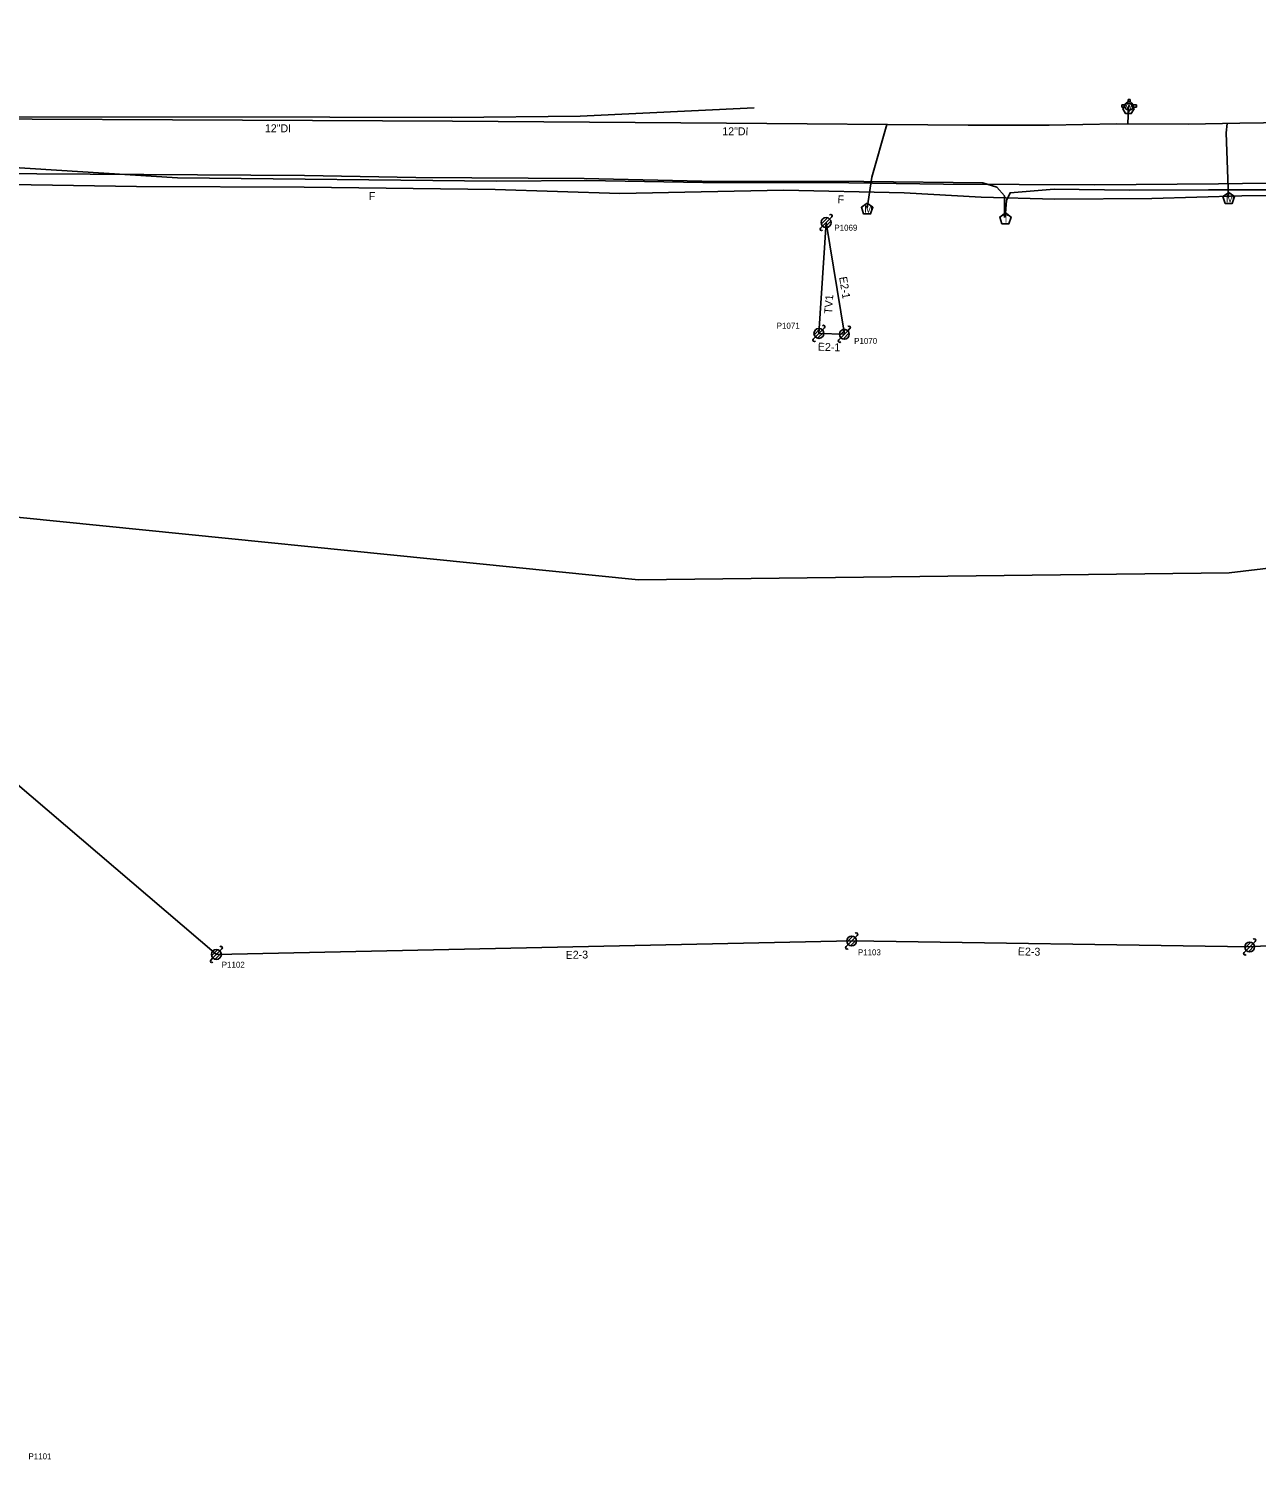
# Model space of a CAD drawing. Extents: x 1614474 to 1865144, y 1098877 to 1212550.
# Drawn here: x 1802379 to 1802999, y 1187603 to 1188326 of the extents above; entities that cross this region are included whole.
import ezdxf

# ---------------------------------------------------------------- set-up
doc = ezdxf.new("R2010")
doc.units = 0
for name, color, linetype in [('BFUSER_FIBERSPAN', 7, 'Continuous'), ('RD_EX_SU_Gas', 7, 'Continuous'), ('RD_EX_SU_H2O', 7, 'Continuous'), ('RD_EX_SU_Ovhd', 7, 'Continuous'), ('RD_EX_SU_Pole', 7, 'Continuous'), ('RD_EX_SU_Telecom', 7, 'Continuous'), ('RD_EX_SU_TX_H2O', 7, 'Continuous'), ('RD_EX_SU_TX_Pole', 7, 'Continuous'), ('RD_EX_SU_TX_Telecom', 7, 'Continuous')]:
    doc.layers.add(name, color=color, linetype=linetype)

# ---------------------------------------------------------------- blocks, each defined once
blk = doc.blocks.new('SUE_TPP')
at = {"layer": 'RD_EX_SU_Telecom'}
blk.add_lwpolyline([(0, 3), (-2.85, 0.93), (-1.76, -2.43), (1.76, -2.43), (2.85, 0.93)], close=True, dxfattribs=at)
blk.add_text('T', height=3.75, dxfattribs=at).set_placement((-1.25, -1.88))
blk = doc.blocks.new('SUE_WV')
at = {"layer": 'RD_EX_SU_H2O'}
blk.add_lwpolyline([(2.89, 0), (1.44, 2.5), (-1.44, 2.5), (-2.89, 0), (-1.44, -2.5), (1.44, -2.5)], close=True, dxfattribs=at)
blk.add_text('V', height=3.75, dxfattribs=at).set_placement((-1.43, -1.88))
blk = doc.blocks.new('SUE_WFH')
at = {"layer": 'RD_EX_SU_H2O'}
for p, q in [((-2.01, 0.6), (-3.65, 0.6)), ((-3.65, 0.6), (-3.65, -0.45)), ((-0.48, 3.38), (-0.48, 2.04)), ((0.57, 3.38), (-0.48, 3.38)), ((0.57, 2.02), (0.57, 3.38)), ((3.7, 0.6), (2.01, 0.6)), ((3.7, -0.45), (3.7, 0.6)), ((-3.65, -0.45), (-2.05, -0.45)), ((2.05, -0.45), (3.7, -0.45))]:
    blk.add_line(p, q, dxfattribs=at)
for radius in [2.1, 0.263]:
    blk.add_circle((0, 0), radius, dxfattribs=at)
for start, end in [(163.3387, 192.31502), (74.24552, 103.21276), (347.68498, 16.6613)]:
    blk.add_arc((0, 0), 2.1, start, end, dxfattribs=at)
blk = doc.blocks.new('SUE_WM')
at = {"layer": 'RD_EX_SU_H2O'}
blk.add_lwpolyline([(0, 3.05), (-2.9, 0.94), (-1.79, -2.47), (1.79, -2.47), (2.9, 0.94)], close=True, dxfattribs=at)
blk.add_text('M', height=3.75, dxfattribs=at).set_placement((-1.43, -1.88))
blk = doc.blocks.new('SUE_PP')
at = {"layer": 'RD_EX_SU_Pole'}
for p, q in [((-2.41, -0.65), (0.65, 2.41)), ((-1.77, -1.77), (1.77, 1.77)), ((-0.65, -2.41), (2.41, 0.65)), ((1.77, 1.77), (2.83, 2.83)), ((-2.83, -2.83), (-1.77, -1.77))]:
    blk.add_line(p, q, dxfattribs=at)
blk.add_circle((0, 0), 2.5, dxfattribs=at)
for centre, start, end in [((2.3, 3.36), 315, 135), ((-2.3, -3.36), 135, 315)]:
    blk.add_arc(centre, 0.75, start, end, dxfattribs=at)

msp = doc.modelspace()

# ---------------------------------------------------------------- linework, layer by layer
at = {"layer": 'BFUSER_FIBERSPAN'}
msp.add_lwpolyline([(1801787.69, 1188212.97), (1801798.88, 1188211.88), (1801776.62, 1188143.66), (1802332.91, 1188082.99), (1802687.07, 1188047.3), (1802985.23, 1188050.78), (1803198.95, 1188076.24)], dxfattribs=at)
at = {"layer": 'RD_EX_SU_Gas'}
msp.add_lwpolyline([(1802035.69, 1188325.53), (1802038.75, 1188311.1), (1802040.95, 1188290.73), (1802043.42, 1188284.85), (1802048.92, 1188285.96), (1802064.02, 1188285.5), (1802120.55, 1188282.05), (1802217.43, 1188282.09), (1802363.14, 1188281), (1802531.2, 1188280.89), (1802592.84, 1188280.65), (1802657.49, 1188281.38), (1802745.41, 1188285.57)], dxfattribs=at)
at = {"layer": 'RD_EX_SU_H2O'}
msp.add_line((1802934.02, 1188277.42), (1802934.36, 1188286.11), dxfattribs=at)
for points in [[(1801857.46, 1188285.91), (1801907.01, 1188284.1), (1801950.85, 1188283.21), (1801982.92, 1188283.18), (1802021.22, 1188283.03), (1802053.57, 1188283.05), (1802102.06, 1188281.72), (1802239.26, 1188280.4), (1802593.05, 1188278.81), (1802731.51, 1188277.72), (1802853.5, 1188276.84), (1802894.3, 1188276.72), (1802928.34, 1188277.44), (1802964.61, 1188277.33), (1802990.65, 1188277.72), (1803038.29, 1188278.47)], [(1802802.43, 1188234.93), (1802804.85, 1188250.6), (1802812.38, 1188277.14)], [(1802984.18, 1188277.63), (1802983.75, 1188272.95), (1802984.85, 1188240.4)]]:
    msp.add_lwpolyline(points, dxfattribs=at)
at = {"layer": 'RD_EX_SU_Ovhd'}
for p, q in [((1802778.1, 1188171.63), (1802781.75, 1188227.63)), ((1802781.75, 1188227.63), (1802790.96, 1188171.22)), ((1802778.1, 1188171.63), (1802790.96, 1188171.22)), ((1802152.75, 1188132.38), (1802473.88, 1187858.09)), ((1802995.59, 1187861.88), (1803204.4, 1187874.28)), ((1802473.88, 1187858.09), (1802794.65, 1187864.89)), ((1802794.65, 1187864.89), (1802995.59, 1187861.88))]:
    msp.add_line(p, q, dxfattribs=at)
at = {"layer": 'RD_EX_SU_Pole'}
for p, q in [((1802775.27, 1188168.8), (1802776.33, 1188169.86)), ((1802775.68, 1188170.98), (1802778.74, 1188174.04)), ((1802776.33, 1188169.86), (1802779.87, 1188173.39)), ((1802777.45, 1188169.21), (1802780.51, 1188172.27)), ((1802779.87, 1188173.39), (1802780.93, 1188174.46)), ((1802788.13, 1188168.39), (1802789.2, 1188169.45)), ((1802788.55, 1188170.57), (1802791.61, 1188173.63)), ((1802789.2, 1188169.45), (1802792.73, 1188172.99)), ((1802790.32, 1188168.8), (1802793.38, 1188171.86)), ((1802792.73, 1188172.99), (1802793.79, 1188174.05)), ((1802792.23, 1187864.24), (1802795.29, 1187867.3)), ((1802792.88, 1187863.12), (1802796.41, 1187866.65)), ((1802794, 1187862.47), (1802797.06, 1187865.53)), ((1802796.41, 1187866.65), (1802797.47, 1187867.71)), ((1802471.46, 1187857.44), (1802474.52, 1187860.5)), ((1802472.11, 1187856.32), (1802475.64, 1187859.86)), ((1802473.23, 1187855.67), (1802476.29, 1187858.74)), ((1802475.64, 1187859.86), (1802476.7, 1187860.92)), ((1802791.82, 1187862.06), (1802792.88, 1187863.12)), ((1802992.76, 1187859.05), (1802993.82, 1187860.11)), ((1802993.17, 1187861.23), (1802996.24, 1187864.29)), ((1802993.82, 1187860.11), (1802997.36, 1187863.65)), ((1802994.94, 1187859.46), (1802998, 1187862.53)), ((1802997.36, 1187863.65), (1802998.42, 1187864.71)), ((1802471.05, 1187855.26), (1802472.11, 1187856.32))]:
    msp.add_line(p, q, dxfattribs=at)
for centre in [(1802778.1, 1188171.63), (1802790.96, 1188171.22), (1802794.65, 1187864.89), (1802473.88, 1187858.09), (1802995.59, 1187861.88)]:
    msp.add_circle(centre, 2.5, dxfattribs=at)
for centre, start, end in [((1802775.8, 1188168.27), 135, 315), ((1802780.4, 1188174.99), 315, 135), ((1802793.26, 1188174.58), 315, 135), ((1802788.66, 1188167.86), 135, 315), ((1802796.94, 1187868.25), 315, 135), ((1802997.89, 1187865.24), 315, 135), ((1802476.17, 1187861.45), 315, 135), ((1802792.35, 1187861.53), 135, 315), ((1802993.29, 1187858.52), 135, 315), ((1802471.58, 1187854.73), 135, 315)]:
    msp.add_arc(centre, 0.75, start, end, dxfattribs=at)
at = {"layer": 'RD_EX_SU_Telecom'}
for points in [[(1801862.35, 1188317.37), (1801873.43, 1188312.99), (1801883.86, 1188304.45), (1801891.39, 1188294.55), (1801895.78, 1188281.09), (1801898.32, 1188280.05), (1801896.15, 1188256.89), (1801899.35, 1188255.07), (1801932.38, 1188254.92), (1801976.57, 1188255.02), (1802034.35, 1188254.03), (1802096.1, 1188253.61), (1802230.47, 1188252.94), (1802355.95, 1188252.37), (1802518.32, 1188251.31), (1802574.51, 1188250.38), (1802659.53, 1188249.82), (1802718.99, 1188248.54), (1802800.77, 1188248.26), (1802860.92, 1188247.72), (1802867.92, 1188245.53), (1802871.84, 1188241.03), (1802871.83, 1188230.11)], [(1801968.17, 1188243.8), (1801975.11, 1188252.56), (1801995.47, 1188251.98), (1802119.14, 1188251.93), (1802254.07, 1188252.11), (1802355.76, 1188256.39), (1802454.16, 1188250.22), (1802615.38, 1188248.45), (1802660.58, 1188248.77), (1802719.54, 1188247.91), (1802781.2, 1188247.75), (1802841.08, 1188246.91), (1802917.35, 1188246.59), (1802979.82, 1188247.18), (1803040.76, 1188247.99), (1803094.59, 1188247.87), (1803108.84, 1188247.38), (1803112.58, 1188243.21)], [(1801967.37, 1188243.92), (1801984.85, 1188243.7), (1802015.11, 1188247.25), (1802055.06, 1188247.37), (1802097.38, 1188247.06), (1802166.97, 1188247.83), (1802252.78, 1188247.03), (1802337.76, 1188247.32), (1802433.59, 1188245.79), (1802518.24, 1188245.41), (1802614.63, 1188244.32), (1802677.58, 1188242.3), (1802718.6, 1188243.19), (1802760.44, 1188243.9), (1802821.17, 1188242.63), (1802859.98, 1188240.47), (1802897.26, 1188239.34), (1802946.24, 1188239.68), (1802991.69, 1188241.06), (1803061.1, 1188241.67)], [(1802872.16, 1188230.26), (1802872.81, 1188238.73), (1802874.65, 1188242.69), (1802896.97, 1188244.53), (1802935, 1188243.9), (1802974.87, 1188244.14), (1803007.78, 1188244.14), (1803058.19, 1188245.26), (1803106.18, 1188244.65), (1803115.09, 1188243.42), (1803117.49, 1188239.07)]]:
    msp.add_lwpolyline(points, dxfattribs=at)

# ---------------------------------------------------------------- block references
at = {"layer": 'RD_EX_SU_H2O'}
for name, p in [('SUE_WFH', (1802934.7, 1188286.4)), ('SUE_WV', (1802934.41, 1188285.09)), ('SUE_WM', (1802985.03, 1188239.76)), ('SUE_WM', (1802802.44, 1188234.42))]:
    msp.add_blockref(name, p, dxfattribs=at)
at = {"layer": 'RD_EX_SU_Pole'}
msp.add_blockref('SUE_PP', (1802781.75, 1188227.63), dxfattribs=at)
at = {"layer": 'RD_EX_SU_Telecom'}
msp.add_blockref('SUE_TPP', (1802872.28, 1188229.47), dxfattribs=at)

# ---------------------------------------------------------------- texts
at = {"layer": 'RD_EX_SU_Ovhd'}
for s, rotation, p in [('E2-1', 279.27619, (1802788.29, 1188200)), ('TV1', 86.26999, (1802784.75, 1188181.37)), ('E2-1', 358.17756, (1802777.52, 1188162.96)), ('E2-3', 1.21385, (1802650.3, 1187855.83)), ('E2-3', 359.14258, (1802878.56, 1187857.63))]:
    msp.add_text(s, height=4, rotation=rotation, dxfattribs=at).set_placement(p)
at = {"layer": 'RD_EX_SU_TX_H2O'}
for rotation, p in [(359.74357, (1802498.38, 1188273.24)), (359.58944, (1802729.32, 1188271.73))]:
    msp.add_text('12"DI', height=4, rotation=rotation, dxfattribs=at).set_placement(p)
at = {"layer": 'RD_EX_SU_TX_Pole'}
for s, p in [('P1069', (1802785.92, 1188223.51)), ('P1071', (1802756.8, 1188174.03)), ('P1070', (1802795.91, 1188166.36)), ('P1103', (1802797.78, 1187857.68)), ('P1102', (1802476.59, 1187851.42)), ('P1101', (1802379.01, 1187603.21))]:
    msp.add_text(s, height=3, dxfattribs=at).set_placement(p)
at = {"layer": 'RD_EX_SU_TX_Telecom'}
for rotation, p in [(359.34987, (1802550.85, 1188239.04)), (358.80659, (1802787.5, 1188237.33))]:
    msp.add_text('F', height=4, rotation=rotation, dxfattribs=at).set_placement(p)

doc.saveas('drawing.dxf')
